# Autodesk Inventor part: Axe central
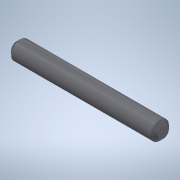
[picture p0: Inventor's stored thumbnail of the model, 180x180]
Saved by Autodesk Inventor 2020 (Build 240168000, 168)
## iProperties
Created: 2002-01
Part Number: Axe central
Material: Acier, doux
Document SubType Name: Modélisation
Designer: Philippe
Mass: 0.0484681 g
Surface Area: 0.258633 cm^2
Volume: 0.00617428 cm^3
Density: 7.85 g/cm^3
Appearance: Métal - Acier (poli)
Shininess: 60.0
Angle Display Precision: 2
Document Length Units: 11269
Document Angle Units: 11279
Document Time Units: 11290
Document Mass Units: 11283
Document Length Units Precision: 3
Document Angle Units Precision: 2
Density: 0.0
Volumn: 0.0
Area: 0.0
PropertySet Name: Model Information
Control State: 0
Master: False
Checked Out: False
Author: Philippe
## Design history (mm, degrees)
node "Esquisse1"
sketch "Esquisse2"
  geometry: L1 (0, 0)-(8, 0); L2 (8, 0)-(8, 0.5); L3 (8, 0.5)-(0, 0.5); L4 (0, 0.5)-(0, 0)
  constraints: 8 end point, 2 parallel, 1 horizontal, 1 perpendicular, 1 other
  dimensions: "d0" = 8 distance of L2.end L3.end; "d1" = 1 diameter of L3 L1
revolve "Révolution1" sketch "Esquisse2" stored, may be unused: angle "d2" = 90 deg
chamfer "Chanfrein1" distance "d3" = 0.2; stored, may be unused: second distance "d4" = 0.2, angle "d5" = 45 deg
node "Solide1"
node "Corps solides"
node "Corps surfaciques"
